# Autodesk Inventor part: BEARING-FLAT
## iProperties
Created: 2007-10
Part Number: BEARING-FLAT
Document SubType Name: Modeling
Material: Delrin, Black
Density: 1.425 g/cm^3
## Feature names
1. Base1
